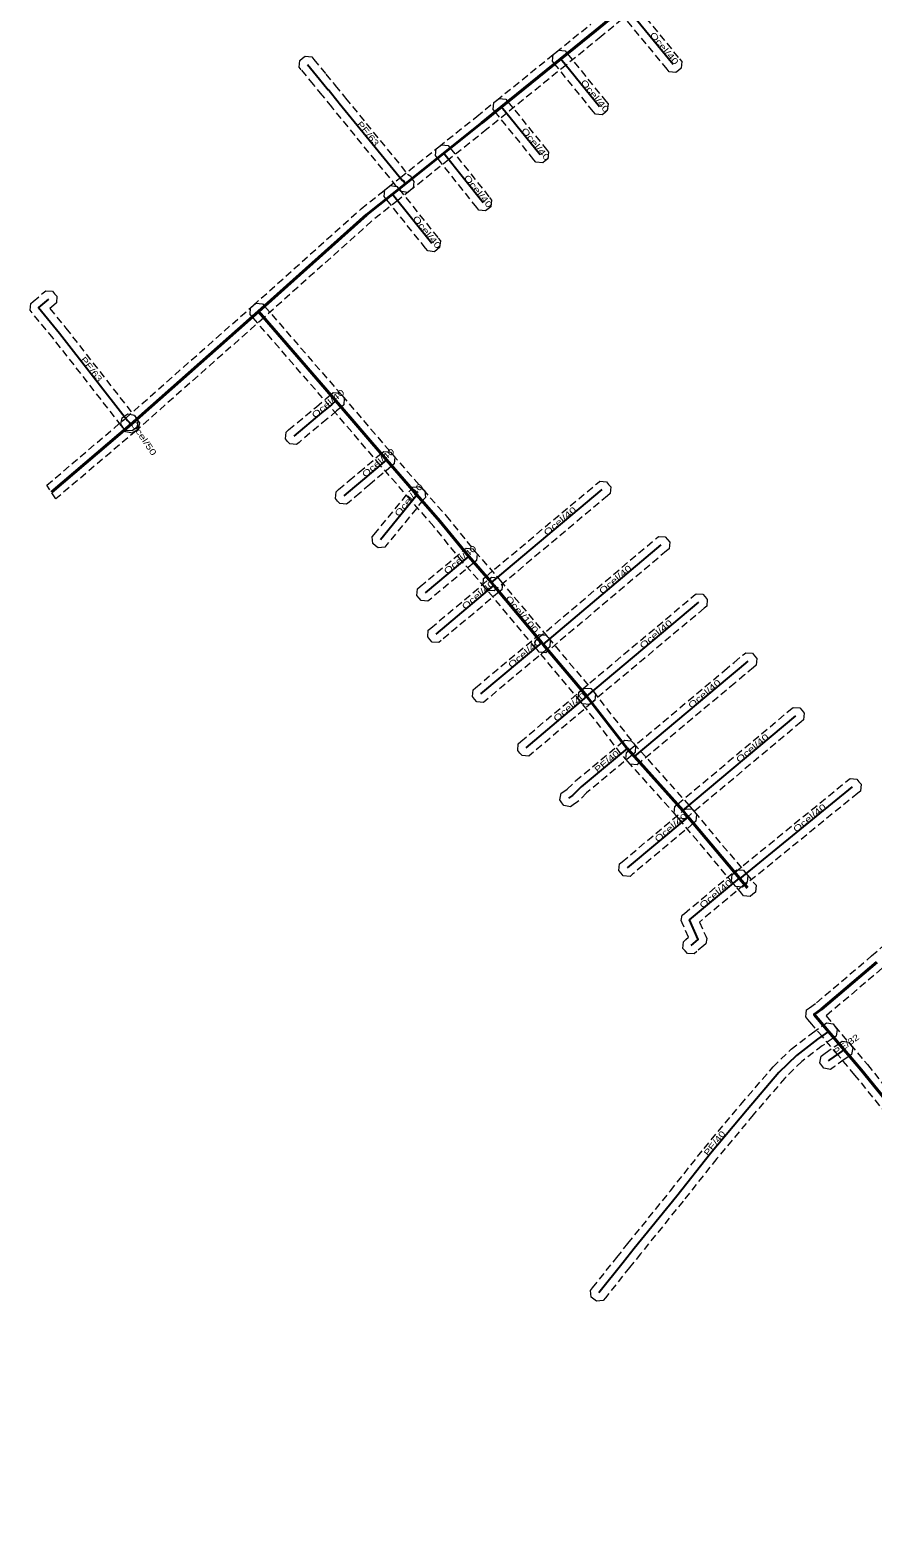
# Model space of a CAD drawing. Extents: x -588392 to -586332, y -1208963 to -1206334.
# Drawn here: x -588347.5 to -588243.8, y -1206733.6 to -1206548.1 of the extents above; entities that cross this region are included whole.
import ezdxf

# ---------------------------------------------------------------- set-up
doc = ezdxf.new("R2010")
doc.units = 0
doc.header["$LTSCALE"] = 0.3
doc.linetypes.add('MEDIUM_DASHED', pattern=[4.5, 3, -1.5])
for name, color, linetype, lineweight in [('1', 7, 'MEDIUM_DASHED', 13), ('14', 7, 'Continuous', 25), ('24', 7, 'Continuous', 25)]:
    doc.layers.add(name, color=color, linetype=linetype, lineweight=lineweight)
doc.layers.add('20', color=7, linetype='Continuous')
doc.layers.add('30', color=7, linetype='Continuous')

msp = doc.modelspace()

# ---------------------------------------------------------------- linework, layer by layer
at = {"layer": '1'}
for points in [[(-588273.741, -1206544.214), (-588273.478, -1206544.534), (-588267.598, -1206551.674), (-588267.335, -1206551.994), (-588267.414, -1206552.819), (-588267.734, -1206553.082), (-588268.054, -1206553.345), (-588268.879, -1206553.266), (-588269.142, -1206552.946), (-588275.022, -1206545.806), (-588275.285, -1206545.486), (-588275.206, -1206544.661), (-588274.886, -1206544.398), (-588274.566, -1206544.135)], [(-588302.087, -1206567.679), (-588302.298, -1206567.418), (-588302.389, -1206567.362), (-588310.261, -1206557.712), (-588310.372, -1206557.561), (-588311.448, -1206556.233), (-588311.555, -1206556.116), (-588312.633, -1206554.805), (-588314.112, -1206553.005), (-588314.375, -1206552.685), (-588314.295, -1206551.861), (-588313.975, -1206551.598), (-588313.655, -1206551.335), (-588312.831, -1206551.415), (-588312.568, -1206551.735), (-588311.087, -1206553.535), (-588310.045, -1206554.804), (-588309.932, -1206554.927), (-588308.788, -1206556.339), (-588308.679, -1206556.488), (-588301.051, -1206565.838), (-588300.649, -1206566.087), (-588300.57, -1206566.375), (-588300.533, -1206566.421), (-588300.272, -1206566.743), (-588300.359, -1206567.566), (-588300.681, -1206567.827), (-588301.003, -1206568.088), (-588301.826, -1206568.001)], [(-588281.674, -1206550.699), (-588281.413, -1206551.021), (-588276.663, -1206556.891), (-588276.402, -1206557.213), (-588276.489, -1206558.036), (-588276.811, -1206558.297), (-588277.133, -1206558.558), (-588277.956, -1206558.471), (-588278.217, -1206558.149), (-588282.967, -1206552.279), (-588283.228, -1206551.957), (-588283.141, -1206551.134), (-588282.819, -1206550.873), (-588282.497, -1206550.612)], [(-588288.974, -1206556.619), (-588288.713, -1206556.941), (-588283.963, -1206562.811), (-588283.702, -1206563.133), (-588283.789, -1206563.956), (-588284.111, -1206564.217), (-588284.433, -1206564.478), (-588285.256, -1206564.391), (-588285.517, -1206564.069), (-588290.267, -1206558.199), (-588290.528, -1206557.877), (-588290.441, -1206557.054), (-588290.119, -1206556.793), (-588289.797, -1206556.532)], [(-588296.067, -1206562.322), (-588295.809, -1206562.646), (-588290.969, -1206568.706), (-588290.711, -1206569.03), (-588290.802, -1206569.853), (-588291.126, -1206570.111), (-588291.45, -1206570.369), (-588292.273, -1206570.278), (-588292.531, -1206569.954), (-588297.371, -1206563.894), (-588297.629, -1206563.57), (-588297.538, -1206562.747), (-588297.214, -1206562.489), (-588296.89, -1206562.231)], [(-588302.357, -1206567.352), (-588302.099, -1206567.676), (-588297.269, -1206573.726), (-588297.011, -1206574.05), (-588297.102, -1206574.873), (-588297.426, -1206575.131), (-588297.75, -1206575.389), (-588298.573, -1206575.298), (-588298.831, -1206574.974), (-588303.661, -1206568.924), (-588303.919, -1206568.6), (-588303.828, -1206567.777), (-588303.504, -1206567.519), (-588303.18, -1206567.261)], [(-588344.231, -1206581.693), (-588344.544, -1206581.965), (-588345.031, -1206582.388), (-588343.059, -1206584.795), (-588334.695, -1206595.508), (-588334.479, -1206595.762), (-588334.21, -1206596.077), (-588334.276, -1206596.903), (-588334.592, -1206597.171), (-588334.907, -1206597.44), (-588335.733, -1206597.374), (-588336.001, -1206597.058), (-588336.245, -1206596.772), (-588344.621, -1206586.045), (-588347.194, -1206582.904), (-588347.451, -1206582.59), (-588347.382, -1206581.781), (-588347.076, -1206581.515), (-588345.856, -1206580.455), (-588345.543, -1206580.183), (-588344.717, -1206580.241), (-588344.445, -1206580.554), (-588344.173, -1206580.867)], [(-588274.81, -1206637.14), (-588279.74, -1206630.754), (-588279.758, -1206630.736), (-588285.296, -1206624.143), (-588291.186, -1206617.113), (-588291.499, -1206616.741), (-588294.295, -1206613.534), (-588297.825, -1206609.184), (-588300.643, -1206605.958), (-588304.407, -1206601.644), (-588310.618, -1206594.393), (-588320.136, -1206583.415), (-588320.407, -1206583.102), (-588320.348, -1206582.276), (-588320.035, -1206582.004), (-588319.722, -1206581.733), (-588318.896, -1206581.792), (-588318.624, -1206582.105), (-588309.102, -1206593.087), (-588302.893, -1206600.336), (-588299.137, -1206604.642), (-588296.295, -1206607.896), (-588292.765, -1206612.246), (-588289.981, -1206615.439), (-588289.654, -1206615.827), (-588283.764, -1206622.857), (-588278.28, -1206629.386), (-588278.238, -1206629.428), (-588273.27, -1206635.86), (-588272.412, -1206636.821), (-588266.462, -1206643.478), (-588265.782, -1206644.3), (-588259.467, -1206651.818), (-588259.407, -1206651.897), (-588258.465, -1206653.016), (-588258.198, -1206653.333), (-588258.269, -1206654.158), (-588258.586, -1206654.425), (-588258.903, -1206654.692), (-588259.728, -1206654.621), (-588259.995, -1206654.304), (-588260.973, -1206653.143), (-588261.033, -1206653.062), (-588267.318, -1206645.58), (-588267.978, -1206644.782), (-588273.904, -1206638.153)], [(-588308.895, -1206594.229), (-588309.209, -1206594.499), (-588309.773, -1206594.982), (-588310.977, -1206595.996), (-588314.389, -1206598.847), (-588314.707, -1206599.113), (-588315.531, -1206599.039), (-588315.797, -1206598.721), (-588316.063, -1206598.403), (-588315.989, -1206597.579), (-588315.671, -1206597.313), (-588312.263, -1206594.464), (-588311.067, -1206593.458), (-588310.511, -1206592.981), (-588310.197, -1206592.711), (-588309.371, -1206592.775), (-588309.101, -1206593.089), (-588308.831, -1206593.403)], [(-588334.638, -1206595.51), (-588334.408, -1206595.855), (-588334.248, -1206596.095), (-588334.018, -1206596.44), (-588334.18, -1206597.252), (-588334.525, -1206597.482), (-588334.87, -1206597.712), (-588335.682, -1206597.55), (-588335.912, -1206597.205), (-588336.072, -1206596.965), (-588336.302, -1206596.62), (-588336.14, -1206595.808), (-588335.795, -1206595.578), (-588335.45, -1206595.348)], [(-588302.689, -1206601.487), (-588303.005, -1206601.754), (-588305.703, -1206604.033), (-588306.922, -1206605.072), (-588308.234, -1206606.183), (-588308.55, -1206606.451), (-588309.375, -1206606.382), (-588309.643, -1206606.066), (-588309.911, -1206605.75), (-588309.842, -1206604.925), (-588309.526, -1206604.657), (-588308.218, -1206603.548), (-588306.997, -1206602.507), (-588304.295, -1206600.226), (-588303.979, -1206599.959), (-588303.153, -1206600.029), (-588302.886, -1206600.345), (-588302.619, -1206600.661)], [(-588291.7, -1206615.59), (-588291.383, -1206615.324), (-588277.743, -1206603.884), (-588277.425, -1206603.618), (-588276.6, -1206603.69), (-588276.334, -1206604.007), (-588276.068, -1206604.325), (-588276.14, -1206605.15), (-588276.457, -1206605.416), (-588290.097, -1206616.856), (-588290.415, -1206617.122), (-588291.24, -1206617.05), (-588291.506, -1206616.733), (-588291.772, -1206616.415)], [(-588305.407, -1206610.479), (-588305.145, -1206610.158), (-588300.665, -1206604.668), (-588300.403, -1206604.347), (-588299.579, -1206604.263), (-588299.258, -1206604.525), (-588298.937, -1206604.787), (-588298.853, -1206605.611), (-588299.115, -1206605.932), (-588303.595, -1206611.422), (-588303.857, -1206611.743), (-588304.681, -1206611.827), (-588305.002, -1206611.565), (-588305.323, -1206611.303)], [(-588285.329, -1206623.196), (-588285.013, -1206622.929), (-588270.496, -1206610.671), (-588270.18, -1206610.404), (-588269.354, -1206610.474), (-588269.087, -1206610.79), (-588268.82, -1206611.106), (-588268.89, -1206611.932), (-588269.206, -1206612.199), (-588283.723, -1206624.457), (-588284.039, -1206624.724), (-588284.865, -1206624.654), (-588285.132, -1206624.338), (-588285.399, -1206624.022)], [(-588299.82, -1206616.849), (-588299.502, -1206616.583), (-588294.172, -1206612.123), (-588293.854, -1206611.857), (-588293.029, -1206611.93), (-588292.763, -1206612.248), (-588292.497, -1206612.566), (-588292.57, -1206613.391), (-588292.888, -1206613.657), (-588298.218, -1206618.117), (-588298.536, -1206618.383), (-588299.361, -1206618.31), (-588299.627, -1206617.992), (-588299.893, -1206617.674)], [(-588298.5, -1206621.95), (-588298.183, -1206621.684), (-588291.063, -1206615.704), (-588290.746, -1206615.438), (-588289.92, -1206615.51), (-588289.654, -1206615.827), (-588289.388, -1206616.144), (-588289.46, -1206616.97), (-588289.777, -1206617.236), (-588296.897, -1206623.216), (-588297.214, -1206623.482), (-588298.04, -1206623.41), (-588298.306, -1206623.093), (-588298.572, -1206622.776)], [(-588279.98, -1206629.56), (-588279.663, -1206629.294), (-588265.873, -1206617.724), (-588265.556, -1206617.458), (-588264.73, -1206617.53), (-588264.464, -1206617.847), (-588264.198, -1206618.164), (-588264.27, -1206618.99), (-588264.587, -1206619.256), (-588278.377, -1206630.826), (-588278.694, -1206631.092), (-588279.52, -1206631.02), (-588279.786, -1206630.703), (-588280.052, -1206630.386)], [(-588293, -1206629.289), (-588292.682, -1206629.023), (-588285.172, -1206622.733), (-588284.854, -1206622.467), (-588284.029, -1206622.54), (-588283.763, -1206622.858), (-588283.497, -1206623.176), (-588283.57, -1206624.001), (-588283.888, -1206624.267), (-588291.398, -1206630.557), (-588291.716, -1206630.823), (-588292.541, -1206630.75), (-588292.807, -1206630.432), (-588293.073, -1206630.114)], [(-588274.118, -1206636.986), (-588273.8, -1206636.72), (-588262.093, -1206626.914), (-588260.893, -1206625.904), (-588259.792, -1206624.983), (-588259.474, -1206624.717), (-588258.649, -1206624.79), (-588258.383, -1206625.108), (-588258.117, -1206625.426), (-588258.19, -1206626.251), (-588258.508, -1206626.517), (-588259.607, -1206627.436), (-588260.807, -1206628.446), (-588272.516, -1206638.254), (-588272.833, -1206638.52), (-588273.659, -1206638.447), (-588273.925, -1206638.129), (-588274.191, -1206637.812)], [(-588287.431, -1206635.914), (-588287.115, -1206635.646), (-588279.635, -1206629.326), (-588279.319, -1206629.059), (-588278.494, -1206629.129), (-588278.226, -1206629.445), (-588277.959, -1206629.761), (-588278.029, -1206630.586), (-588278.345, -1206630.854), (-588285.825, -1206637.174), (-588286.141, -1206637.441), (-588286.966, -1206637.371), (-588287.234, -1206637.055), (-588287.501, -1206636.739)], [(-588268.18, -1206643.63), (-588267.862, -1206643.364), (-588253.952, -1206631.704), (-588253.635, -1206631.438), (-588252.81, -1206631.51), (-588252.544, -1206631.828), (-588252.278, -1206632.145), (-588252.35, -1206632.97), (-588252.668, -1206633.236), (-588266.578, -1206644.896), (-588266.895, -1206645.162), (-588267.72, -1206645.09), (-588267.986, -1206644.772), (-588268.252, -1206644.455)], [(-588273.081, -1206637.002), (-588273.399, -1206637.268), (-588279.037, -1206641.971), (-588280.141, -1206643.065), (-588280.687, -1206643.437), (-588281.03, -1206643.67), (-588281.844, -1206643.515), (-588282.077, -1206643.173), (-588282.31, -1206642.83), (-588282.155, -1206642.016), (-588281.813, -1206641.783), (-588281.419, -1206641.515), (-588280.383, -1206640.489), (-588274.681, -1206635.732), (-588274.363, -1206635.467), (-588273.538, -1206635.541), (-588273.272, -1206635.859), (-588273.007, -1206636.177)], [(-588261.143, -1206652.006), (-588260.822, -1206651.745), (-588246.952, -1206640.445), (-588246.631, -1206640.183), (-588245.806, -1206640.267), (-588245.545, -1206640.588), (-588245.283, -1206640.909), (-588245.367, -1206641.734), (-588245.688, -1206641.995), (-588259.558, -1206653.295), (-588259.879, -1206653.557), (-588260.704, -1206653.473), (-588260.965, -1206653.152), (-588261.227, -1206652.831)], [(-588274.98, -1206650.7), (-588274.662, -1206650.434), (-588267.192, -1206644.174), (-588266.875, -1206643.908), (-588266.05, -1206643.98), (-588265.784, -1206644.298), (-588265.518, -1206644.615), (-588265.59, -1206645.44), (-588265.908, -1206645.706), (-588273.378, -1206651.966), (-588273.695, -1206652.232), (-588274.52, -1206652.16), (-588274.786, -1206651.842), (-588275.052, -1206651.525)], [(-588267.133, -1206660.265), (-588266.822, -1206659.991), (-588266.51, -1206659.715), (-588267.285, -1206657.964), (-588267.42, -1206657.658), (-588267.268, -1206657.008), (-588267.012, -1206656.793), (-588260.892, -1206651.673), (-588260.574, -1206651.407), (-588259.749, -1206651.48), (-588259.483, -1206651.798), (-588259.217, -1206652.116), (-588259.29, -1206652.941), (-588259.608, -1206653.207), (-588265.151, -1206657.844), (-588264.385, -1206659.576), (-588264.253, -1206659.875), (-588264.393, -1206660.513), (-588264.638, -1206660.729), (-588265.498, -1206661.489), (-588265.808, -1206661.764), (-588266.635, -1206661.713), (-588266.909, -1206661.402), (-588267.184, -1206661.092)], [(-588248.363, -1206671.876), (-588248.701, -1206672.115), (-588250.057, -1206673.076), (-588252.584, -1206675.007), (-588254.649, -1206677.034), (-588258.547, -1206681.576), (-588263.034, -1206686.951), (-588267.169, -1206692.174), (-588272.391, -1206698.647), (-588273.759, -1206700.354), (-588276.728, -1206704.083), (-588276.986, -1206704.407), (-588277.809, -1206704.5), (-588278.133, -1206704.242), (-588278.457, -1206703.984), (-588278.55, -1206703.161), (-588278.292, -1206702.837), (-588275.321, -1206699.106), (-588273.949, -1206697.393), (-588268.731, -1206690.926), (-588264.586, -1206685.689), (-588260.073, -1206680.284), (-588256.111, -1206675.666), (-588253.896, -1206673.493), (-588251.243, -1206671.464), (-588249.857, -1206670.483), (-588249.519, -1206670.244), (-588248.702, -1206670.383), (-588248.463, -1206670.721), (-588248.224, -1206671.059)], [(-588250.211, -1206674.352), (-588249.875, -1206674.109), (-588249.692, -1206673.977), (-588248.519, -1206673.144), (-588247.947, -1206672.739), (-588247.609, -1206672.499), (-588246.792, -1206672.637), (-588246.553, -1206672.975), (-588246.313, -1206673.313), (-588246.451, -1206674.13), (-588246.789, -1206674.369), (-588247.361, -1206674.776), (-588248.528, -1206675.603), (-588248.705, -1206675.731), (-588249.041, -1206675.973), (-588249.858, -1206675.841), (-588250.101, -1206675.505), (-588250.343, -1206675.169)]]:
    msp.add_lwpolyline(points, close=True, dxfattribs=at)
for points in [[(-588273.615, -1206545.942), (-588277.247, -1206548.935), (-588281.56, -1206552.427), (-588288.859, -1206558.346), (-588291.283, -1206560.319), (-588295.966, -1206564.051), (-588300.686, -1206567.831), (-588302.257, -1206569.082), (-588305.464, -1206571.634), (-588318.715, -1206583.507), (-588334.425, -1206597.405), (-588344.288, -1206605.796), (-588345.401, -1206604.118), (-588335.735, -1206595.895), (-588320.045, -1206582.013), (-588306.756, -1206570.106), (-588303.503, -1206567.518), (-588301.934, -1206566.269), (-588297.214, -1206562.489), (-588292.537, -1206558.761), (-588290.121, -1206556.794), (-588282.82, -1206550.873), (-588278.513, -1206547.385)], [(-588125.407, -1206687.292), (-588130.441, -1206681.277), (-588137.957, -1206672.07), (-588138.584, -1206671.301), (-588143.866, -1206664.83), (-588151.779, -1206655.029), (-588152.516, -1206654.116), (-588155.385, -1206650.562), (-588163.311, -1206640.947), (-588165.184, -1206638.673), (-588166.433, -1206637.137), (-588176.577, -1206624.661), (-588181.505, -1206618.6), (-588183.31, -1206616.38), (-588184.525, -1206614.885), (-588189.94, -1206619.147), (-588199.779, -1206627.347), (-588208.698, -1206634.827), (-588218.243, -1206642.793), (-588227.136, -1206650.465), (-588235.646, -1206657.455), (-588242.69, -1206663.54), (-588249.533, -1206669.348)], [(-588242.133, -1206681.487), (-588246.04, -1206676.668), (-588248.131, -1206674.2), (-588250.042, -1206671.946), (-588251.351, -1206670.402), (-588251.813, -1206669.857), (-588252.095, -1206669.523), (-588252.043, -1206669.089), (-588251.99, -1206668.655), (-588251.635, -1206668.399), (-588250.767, -1206667.772), (-588243.99, -1206662.02), (-588236.934, -1206655.925)], [(-588249.533, -1206669.348), (-588249.588, -1206669.388), (-588248.516, -1206670.652), (-588246.605, -1206672.908), (-588244.5, -1206675.392), (-588240.579, -1206680.227), (-588237.634, -1206683.859), (-588230.745, -1206692.316), (-588230.496, -1206692.622), (-588228.534, -1206695.029), (-588220.863, -1206704.491), (-588218.272, -1206707.694), (-588212.832, -1206714.422), (-588208.33, -1206720.016), (-588205.122, -1206724.001), (-588204.177, -1206725.166), (-588197.003, -1206734)]]:
    msp.add_lwpolyline(points, dxfattribs=at)
at = {"layer": '14'}
for p, q in [((-588274.25, -1206545.17), (-588268.37, -1206552.31)), ((-588282.19, -1206551.65), (-588277.44, -1206557.52)), ((-588289.49, -1206557.57), (-588284.74, -1206563.44)), ((-588296.59, -1206563.27), (-588291.75, -1206569.33)), ((-588302.88, -1206568.3), (-588298.05, -1206574.35)), ((-588304.37, -1206610.79), (-588299.89, -1206605.3)), ((-588290.74, -1206616.09), (-588277.1, -1206604.65)), ((-588298.86, -1206617.35), (-588293.53, -1206612.89)), ((-588284.368, -1206623.693), (-588269.851, -1206611.435)), ((-588297.54, -1206622.45), (-588290.42, -1206616.47)), ((-588279.02, -1206630.06), (-588265.23, -1206618.49)), ((-588292.04, -1206629.79), (-588284.53, -1206623.5)), ((-588286.47, -1206636.41), (-588278.99, -1206630.09)), ((-588267.22, -1206644.13), (-588253.31, -1206632.47)), ((-588260.19, -1206652.52), (-588246.32, -1206641.22)), ((-588274.02, -1206651.2), (-588266.55, -1206644.94))]:
    msp.add_line(p, q, dxfattribs=at)
at = {"layer": '14', "lineweight": 40}
for points in [[(-588274.25, -1206545.17), (-588277.88, -1206548.16), (-588282.19, -1206551.65), (-588289.49, -1206557.57), (-588291.91, -1206559.54), (-588296.59, -1206563.27), (-588301.31, -1206567.05), (-588302.88, -1206568.3), (-588306.11, -1206570.87), (-588319.38, -1206582.76), (-588335.08, -1206596.65), (-588344.845, -1206604.957)], [(-588319.38, -1206582.76), (-588309.86, -1206593.74), (-588303.65, -1206600.99), (-588299.89, -1206605.3), (-588297.06, -1206608.54), (-588293.53, -1206612.89), (-588290.74, -1206616.09), (-588290.42, -1206616.47), (-588284.53, -1206623.5), (-588284.368, -1206623.693), (-588279.02, -1206630.06), (-588278.99, -1206630.09), (-588274.04, -1206636.5), (-588273.158, -1206637.487), (-588267.22, -1206644.13), (-588266.55, -1206644.94), (-588260.25, -1206652.44), (-588260.19, -1206652.52), (-588259.23, -1206653.66)]]:
    msp.add_lwpolyline(points, dxfattribs=at)
at = {"layer": '14'}
for points in [[(-588313.34, -1206552.37), (-588311.86, -1206554.17), (-588310.8, -1206555.46), (-588310.69, -1206555.58), (-588309.58, -1206556.95), (-588309.47, -1206557.1), (-588301.72, -1206566.6), (-588301.51, -1206566.73), (-588301.48, -1206566.84), (-588301.31, -1206567.05)], [(-588345.2, -1206581.21), (-588346.42, -1206582.27), (-588343.84, -1206585.42), (-588335.47, -1206596.14), (-588335.24, -1206596.41), (-588335.08, -1206596.65)], [(-588309.86, -1206593.74), (-588310.42, -1206594.22), (-588311.62, -1206595.23), (-588315.03, -1206598.08)], [(-588303.65, -1206600.99), (-588306.35, -1206603.27), (-588307.57, -1206604.31), (-588308.88, -1206605.42)], [(-588273.158, -1206637.487), (-588261.45, -1206627.68), (-588260.25, -1206626.67), (-588259.15, -1206625.75)], [(-588274.04, -1206636.5), (-588279.71, -1206641.23), (-588280.042, -1206641.558), (-588280.524, -1206642.036), (-588280.78, -1206642.29), (-588281.25, -1206642.61)], [(-588266.16, -1206660.74), (-588265.3, -1206659.98), (-588266.37, -1206657.56), (-588260.25, -1206652.44)]]:
    msp.add_lwpolyline(points, dxfattribs=at)
at = {"layer": '24', "lineweight": 40}
msp.add_lwpolyline([(-588241.356, -1206680.857), (-588245.27, -1206676.03), (-588247.368, -1206673.554), (-588249.279, -1206671.299), (-588250.588, -1206669.755), (-588251.05, -1206669.21), (-588250.15, -1206668.56), (-588243.34, -1206662.78)], dxfattribs=at)
at = {"layer": '24'}
for points in [[(-588249.279, -1206671.299), (-588250.65, -1206672.27), (-588253.24, -1206674.25), (-588255.38, -1206676.35), (-588259.31, -1206680.93), (-588263.81, -1206686.32), (-588267.95, -1206691.55), (-588273.17, -1206698.02), (-588274.54, -1206699.73), (-588277.51, -1206703.46)], [(-588249.29, -1206674.92), (-588249.11, -1206674.79), (-588248.585, -1206674.418), (-588247.94, -1206673.96), (-588247.368, -1206673.554)]]:
    msp.add_lwpolyline(points, dxfattribs=at)

# ---------------------------------------------------------------- texts
at = {"layer": '20'}
for s, rotation, width, p in [('Ocel/40', 309.472, 1.4, (-588271.31, -1206548.74)), ('Ocel/40', 308.98, 1.4, (-588279.815, -1206554.585)), ('PE/63', 309.207, 1.3, (-588307.327, -1206559.726)), ('Ocel/40', 308.98, 1.4, (-588287.115, -1206560.505)), ('Ocel/40', 308.614, 1.4, (-588294.17, -1206566.3)), ('Ocel/40', 308.602, 1.4, (-588300.465, -1206571.325)), ('PE/63', 307.982, 1.3, (-588341.296, -1206588.678)), ('Ocel/40', 39.888, 1.4, (-588312.44, -1206595.915)), ('Ocel/50', 303.69, 1.4, (-588335.16, -1206596.53)), ('Ocel/40', 40.179, 1.4, (-588306.269, -1206603.201)), ('Ocel/40', 50.785, 1.4, (-588302.13, -1206608.045)), ('Ocel/40', 39.987, 1.4, (-588283.92, -1206610.37)), ('Ocel/40', 39.922, 1.4, (-588296.195, -1206615.12)), ('Ocel/40', 40.177, 1.4, (-588277.11, -1206617.564)), ('Ocel/40', 40.026, 1.4, (-588293.98, -1206619.46)), ('Ocel/100', 309.958, 1.4, (-588289.069, -1206618.082)), ('Ocel/40', 39.997, 1.4, (-588272.125, -1206624.275)), ('Ocel/40', 39.948, 1.4, (-588288.285, -1206626.645)), ('Ocel/40', 40.195, 1.4, (-588282.73, -1206633.25)), ('Ocel/40', 39.951, 1.4, (-588266.153, -1206631.619)), ('Ocel/40', 39.971, 1.4, (-588260.265, -1206638.3)), ('PE/40', 39.835, 1.3, (-588277.672, -1206639.529)), ('Ocel/40', 39.964, 1.4, (-588270.285, -1206648.07)), ('Ocel/40', 39.17, 1.4, (-588253.255, -1206646.87)), ('Ocel/40', 39.916, 1.4, (-588264.765, -1206656.217))]:
    msp.add_text(s, height=0.75, rotation=rotation, dxfattribs=dict(at, width=width)).set_placement(p)
at = {"layer": '30', "width": 1.3}
for s, rotation, p in [('PE/32', 35.378, (-588248.33, -1206674.236)), ('PE/40', 51.635, (-588264.104, -1206686.691))]:
    msp.add_text(s, height=0.75, rotation=rotation, dxfattribs=at).set_placement(p)

doc.saveas('drawing.dxf')
